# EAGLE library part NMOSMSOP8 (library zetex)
MOS FET
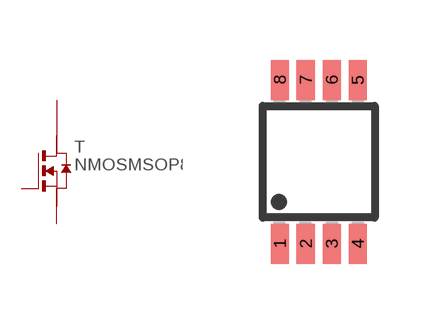
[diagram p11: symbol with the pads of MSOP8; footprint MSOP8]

Designator prefix T

## NMOSMSOP8 (OC_FARNELL: unknown; OC_NEWARK: unknown)  [MSOP8]
1  D  pas
2  D1  pas
3  D2  pas
4  D3  pas
5  S  pas
6  S1  pas
7  S2  pas
8  G  pas

## Footprint MSOP8 (pad centres in mm)
Micro Small Outline Package
smd 0.45 x 1: 1 -0.975,-2.05; 2 -0.325,-2.05; 3 0.325,-2.05; 4 0.975,-2.05; 5 0.975,2.05; 6 0.325,2.05; 7 -0.325,2.05; 8 -0.975,2.05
